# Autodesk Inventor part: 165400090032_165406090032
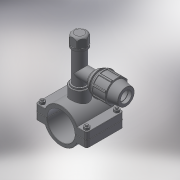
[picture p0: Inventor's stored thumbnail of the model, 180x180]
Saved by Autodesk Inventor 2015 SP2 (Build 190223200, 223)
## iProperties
Created: 2017-05
Part Number: 165400090032_165406090032
Material: Generic
Description: PLASSON TAPPER FOR PE+PVC PIPE 90-32
Document SubType Name: Modeling
Designer: KIM
Density: 1 g/cm^3
Appearance: Default
Author: KIM
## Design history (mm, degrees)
derived "16540.ipt"
feature "Solid1::16540.ipt"
feature "Solid2::16540.ipt"
tag "TaggingFeature1"
body "Solid1"
other parameters: "d0" = 99, "d1" = 141, "d2" = 45, "d4" = 105, "d5" = 0, "d6" = 7.05, "d7" = 141, "d8" = 0.1, "d10" = 0, "d11" = 0.9, "d14" = 50.6376, "d20" = 0.9, "d23" = 0.9, "d36" = 13, "d37" = 10.4, "d38" = 53, "d39" = 0, "d40" = 3, "d41" = 5, "d42" = 0, "d43" = 8, "d44" = 3, "d45" = 0, "d46" = 0.9, "d52" = 38.952, "d53" = 25, "d54" = 0, "d55" = 32, "d57" = 0, "d58" = 97.2, "d60" = 0, "d62" = 13, "d63" = 10.4, "d66" = 84.2, "d67" = 32, "d68" = 9.08333, "d69" = 21.8, "d70" = 64, "d71" = 48, "d72" = 1.55714, "d73" = 51.2, "d74" = 120 deg, "d75" = 48, "d76" = 10 deg, "d77" = 57.6, "d78" = 32.7, "d79" = 71, "d80" = 25.6, "d81" = 109, "d82" = 7.1, "d87" = 15.57143, "d90" = 59.52, "d91" = 35 deg, "d92" = 17.5 deg, "d94" = 0, "d96" = 360 deg, "d98" = 0.64, "d99" = 78.1, "d100" = 35.0568, "d101" = 135 deg, "d102" = 1.28, "d105" = 3.2, "d106" = 0, "d107" = 0.1, "d108" = 35.0568, "d109" = 42.8472, "d111" = 26.2, "d112" = 6.55, "d113" = 3.63333, "d116" = 0, "d117" = 38, "d118" = 21.8, "d119" = 0, "d121" = 131, "d122" = 58, "B_" = 32, "G_" = 38.952, "L_" = 141, "L_1" = 105, "l_2" = 25, "d_1" = 32, "E_" = 64, "l_" = 71, "H_" = 109, "H_1" = 58, "H_2" = 131
